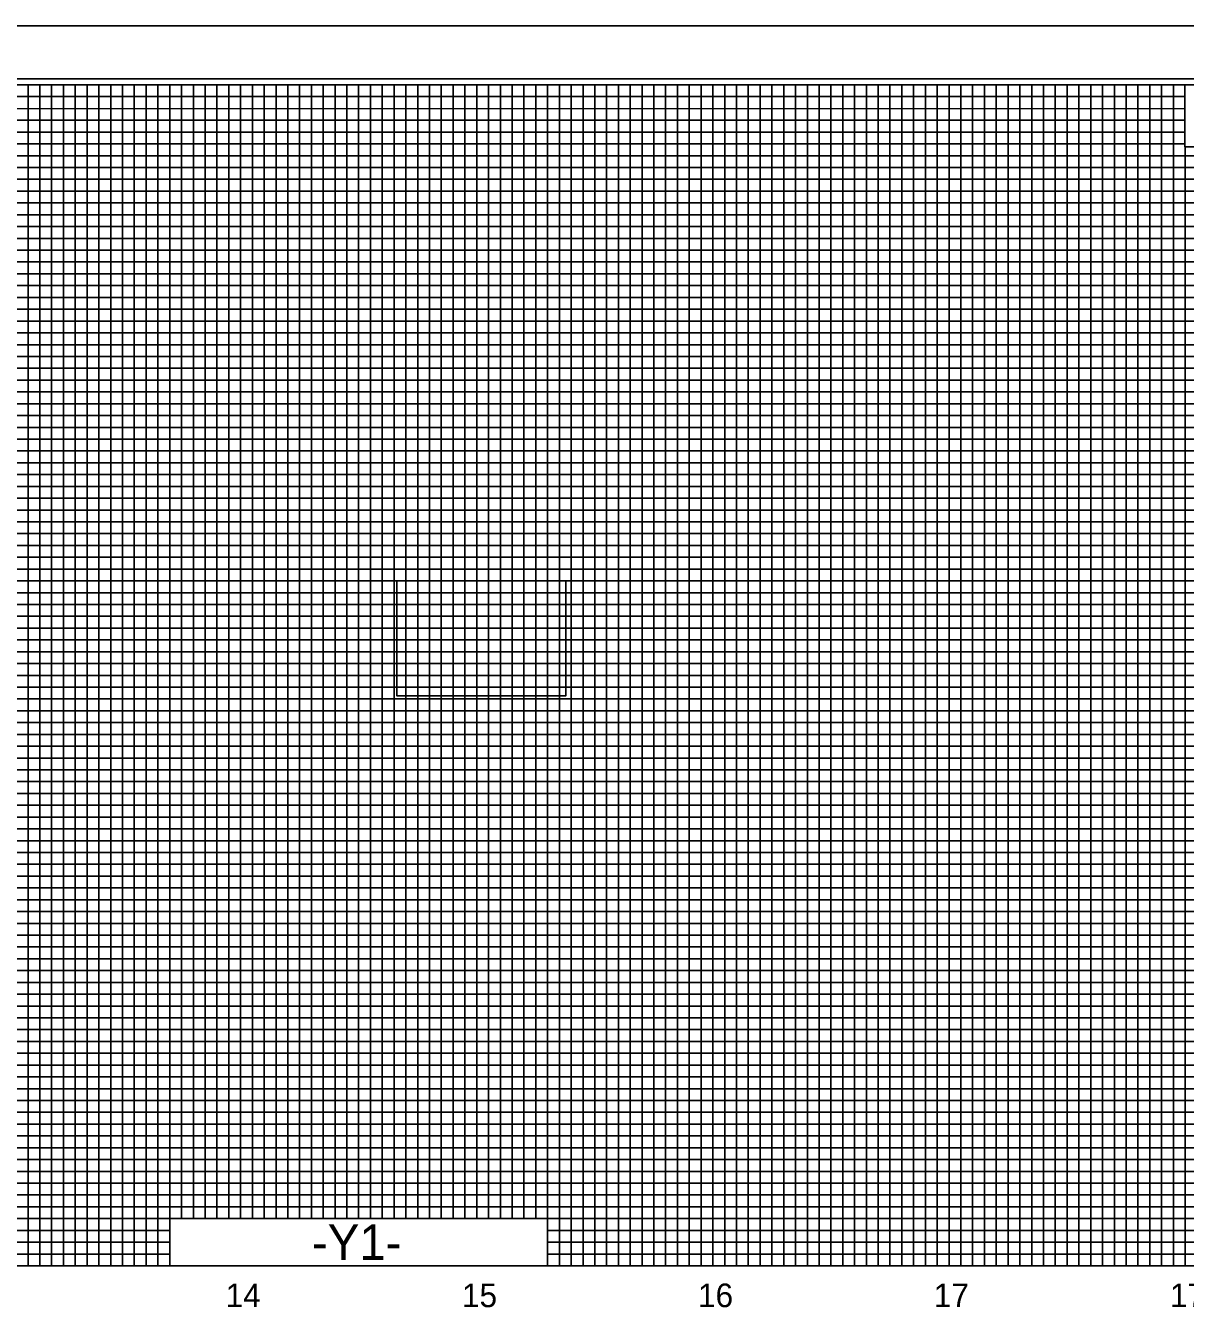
# Model space of a CAD drawing. Extents: x 1629737 to 1631945, y 1172886 to 1173986.
# Drawn here: x 1630513 to 1631004, y 1173440 to 1173986 of the extents above; entities that cross this region are included whole.
import ezdxf

# ---------------------------------------------------------------- set-up
doc = ezdxf.new("R2010")
doc.units = 0
for name, color, linetype in [('Exist Vertical Profile Horizontal Axis Label Major', 7, 'Continuous'), ('Prop Grid Mask', 7, 'Continuous'), ('Sheet Block Title CELL', 7, 'Continuous'), ('Sheet Data Field CELL', 7, 'Continuous'), ('Sheet Layout Profile Border Port 1', 7, 'Continuous'), ('Sheet Plot Border Inside CELL', 7, 'Continuous'), ('Sheet Plot Border Outside CELL', 7, 'Continuous'), ('Sheet Profile CELL', 7, 'Continuous'), ('Sheet Profile Grid Major CELL', 7, 'Continuous'), ('Sheet Profile Grid Middle CELL', 7, 'Continuous'), ('Sheet Profile Grid Minor CELL', 7, 'Continuous')]:
    doc.layers.add(name, color=color, linetype=linetype)

msp = doc.modelspace()

# ---------------------------------------------------------------- linework, layer by layer
at = {"layer": 'Prop Grid Mask'}
msp.add_lwpolyline([(1630670.53, 1173750.94), (1630742.03, 1173750.94), (1630742.03, 1173702.22), (1630670.53, 1173702.22)], close=True, dxfattribs=at)
at = {"layer": 'Sheet Block Title CELL'}
msp.add_lwpolyline([(1631004.21, 1173960.94), (1631204.26, 1173960.94), (1631204.26, 1173934.68), (1631004.21, 1173934.68)], close=True, dxfattribs=at)
at = {"layer": 'Sheet Data Field CELL'}
msp.add_lwpolyline([(1630574.31, 1173460.94), (1630734.31, 1173460.94), (1630734.31, 1173480.94), (1630574.31, 1173480.94)], close=True, dxfattribs=at)
at = {"layer": 'Sheet Layout Profile Border Port 1'}
msp.add_lwpolyline([(1629954.31, 1173960.94), (1631004.21, 1173960.94), (1631004.21, 1173934.68), (1631204.26, 1173934.68), (1631204.26, 1173799.89), (1631354.31, 1173799.89), (1631354.31, 1173485.94), (1631154.31, 1173485.94), (1631154.31, 1173460.94), (1630734.31, 1173460.94), (1630734.31, 1173480.94), (1630574.31, 1173480.94), (1630574.31, 1173460.94), (1629954.31, 1173460.94)], close=True, dxfattribs=at)
at = {"layer": 'Sheet Plot Border Inside CELL'}
msp.add_lwpolyline([(1629750.31, 1172908.39), (1631416.81, 1172908.39), (1631416.81, 1173963.49), (1629750.31, 1173963.49)], close=True, dxfattribs=at)
at = {"layer": 'Sheet Plot Border Outside CELL'}
msp.add_lwpolyline([(1629737.31, 1172885.94), (1631421.31, 1172885.94), (1631421.31, 1173985.94), (1629737.31, 1173985.94)], close=True, dxfattribs=at)
at = {"layer": 'Sheet Profile CELL'}
msp.add_line((1631404.31, 1173460.94), (1629904.31, 1173460.94), dxfattribs=at)
msp.add_lwpolyline([(1631404.31, 1173960.94), (1629904.31, 1173960.94), (1629904.31, 1172910.94), (1631404.31, 1172910.94)], close=True, dxfattribs=at)
at = {"layer": 'Sheet Profile Grid Major CELL'}
for p, q in [((1630504.31, 1173960.94), (1630554.31, 1173960.94)), ((1630554.31, 1173960.94), (1630554.31, 1173460.94)), ((1630604.31, 1173480.94), (1630604.31, 1173960.94)), ((1630604.31, 1173960.94), (1630654.31, 1173960.94)), ((1630654.31, 1173960.94), (1630654.31, 1173480.94)), ((1630704.31, 1173480.94), (1630704.31, 1173960.94)), ((1630704.31, 1173960.94), (1630754.31, 1173960.94)), ((1630754.31, 1173960.94), (1630754.31, 1173460.94)), ((1630804.31, 1173460.94), (1630804.31, 1173960.94)), ((1630804.31, 1173960.94), (1630854.31, 1173960.94)), ((1630854.31, 1173960.94), (1630854.31, 1173460.94)), ((1630904.31, 1173460.94), (1630904.31, 1173960.94)), ((1630904.31, 1173960.94), (1630954.31, 1173960.94)), ((1630954.31, 1173960.94), (1630954.31, 1173460.94)), ((1631004.31, 1173460.94), (1631004.31, 1173934.68)), ((1630554.31, 1173460.94), (1630584.31, 1173460.94)), ((1630754.31, 1173460.94), (1630804.31, 1173460.94)), ((1630854.31, 1173460.94), (1630904.31, 1173460.94)), ((1630954.31, 1173460.94), (1631004.31, 1173460.94))]:
    msp.add_line(p, q, dxfattribs=at)
for points in [[(1629904.31, 1173935.94), (1631004.21, 1173935.94)], [(1629904.31, 1173885.94), (1631204.26, 1173885.94)], [(1631204.26, 1173835.94), (1629904.31, 1173835.94), (1629904.31, 1173785.94), (1631404.31, 1173785.94)], [(1631404.31, 1173735.94), (1629904.31, 1173735.94), (1629904.31, 1173685.94), (1631404.31, 1173685.94)], [(1631404.31, 1173635.94), (1629904.31, 1173635.94), (1629904.31, 1173585.94), (1631404.31, 1173585.94)], [(1631404.31, 1173535.94), (1629904.31, 1173535.94), (1629904.31, 1173535.94), (1629904.31, 1173485.94), (1631404.31, 1173485.94)]]:
    msp.add_lwpolyline(points, dxfattribs=at)
at = {"layer": 'Sheet Profile Grid Middle CELL'}
msp.add_line((1629904.31, 1173960.94), (1631004.21, 1173960.94), dxfattribs=at)
for points in [[(1630479.31, 1173460.94), (1630529.31, 1173460.94), (1630529.31, 1173460.94), (1630529.31, 1173960.94), (1630579.31, 1173960.94), (1630579.31, 1173480.94)], [(1630629.31, 1173480.94), (1630629.31, 1173960.94), (1630679.31, 1173960.94), (1630679.31, 1173480.94)], [(1630729.31, 1173480.94), (1630729.31, 1173960.94), (1630779.31, 1173960.94), (1630779.31, 1173460.94), (1630829.31, 1173460.94), (1630829.31, 1173960.94), (1630879.31, 1173960.94), (1630879.31, 1173460.94), (1630929.31, 1173460.94), (1630929.31, 1173960.94), (1630979.31, 1173960.94), (1630979.31, 1173460.94), (1631029.31, 1173460.94), (1631029.31, 1173934.68)], [(1631204.26, 1173910.94), (1629904.31, 1173910.94), (1629904.31, 1173860.94), (1631204.26, 1173860.94)], [(1631204.26, 1173810.94), (1629904.31, 1173810.94), (1629904.31, 1173760.94), (1631404.31, 1173760.94)], [(1631404.31, 1173710.94), (1629904.31, 1173710.94), (1629904.31, 1173660.94), (1631404.31, 1173660.94)], [(1631404.31, 1173610.94), (1629904.31, 1173610.94), (1629904.31, 1173560.94), (1631404.31, 1173560.94)], [(1631404.31, 1173510.94), (1629904.31, 1173510.94)]]:
    msp.add_lwpolyline(points, dxfattribs=at)
at = {"layer": 'Sheet Profile Grid Minor CELL'}
for p, q in [((1630514.31, 1173460.94), (1630514.31, 1173960.94)), ((1630514.31, 1173960.94), (1630519.31, 1173960.94)), ((1630519.31, 1173960.94), (1630519.31, 1173460.94)), ((1630524.31, 1173460.94), (1630524.31, 1173960.94)), ((1630524.31, 1173960.94), (1630534.31, 1173960.94)), ((1630534.31, 1173960.94), (1630534.31, 1173460.94)), ((1630539.31, 1173460.94), (1630539.31, 1173960.94)), ((1630539.31, 1173960.94), (1630544.31, 1173960.94)), ((1630544.31, 1173960.94), (1630544.31, 1173460.94)), ((1630549.31, 1173460.94), (1630549.31, 1173960.94)), ((1630549.31, 1173960.94), (1630559.31, 1173960.94)), ((1630559.31, 1173960.94), (1630559.31, 1173460.94)), ((1630564.31, 1173460.94), (1630564.31, 1173960.94)), ((1630564.31, 1173960.94), (1630569.31, 1173960.94)), ((1630569.31, 1173960.94), (1630569.31, 1173460.94)), ((1630574.31, 1173460.94), (1630574.31, 1173960.94)), ((1630574.31, 1173960.94), (1630584.31, 1173960.94)), ((1630584.31, 1173960.94), (1630584.31, 1173480.94)), ((1630589.31, 1173480.94), (1630589.31, 1173960.94)), ((1630589.31, 1173960.94), (1630594.31, 1173960.94)), ((1630594.31, 1173960.94), (1630594.31, 1173480.94)), ((1630599.31, 1173480.94), (1630599.31, 1173960.94)), ((1630599.31, 1173960.94), (1630609.31, 1173960.94)), ((1630609.31, 1173960.94), (1630609.31, 1173480.94)), ((1630699.31, 1173480.94), (1630699.31, 1173960.94)), ((1630699.31, 1173960.94), (1630709.31, 1173960.94)), ((1630709.31, 1173960.94), (1630709.31, 1173480.94)), ((1630714.31, 1173480.94), (1630714.31, 1173960.94)), ((1630714.31, 1173960.94), (1630719.31, 1173960.94)), ((1630719.31, 1173960.94), (1630719.31, 1173480.94)), ((1630724.31, 1173480.94), (1630724.31, 1173960.94)), ((1630724.31, 1173960.94), (1630734.31, 1173960.94)), ((1630734.31, 1173960.94), (1630734.31, 1173460.94)), ((1630739.31, 1173460.94), (1630739.31, 1173960.94)), ((1630739.31, 1173960.94), (1630744.31, 1173960.94)), ((1630744.31, 1173960.94), (1630744.31, 1173460.94)), ((1630749.31, 1173460.94), (1630749.31, 1173960.94)), ((1630749.31, 1173960.94), (1630759.31, 1173960.94)), ((1630759.31, 1173960.94), (1630759.31, 1173460.94)), ((1630764.31, 1173460.94), (1630764.31, 1173960.94)), ((1630764.31, 1173960.94), (1630769.31, 1173960.94)), ((1630769.31, 1173960.94), (1630769.31, 1173460.94)), ((1630774.31, 1173460.94), (1630774.31, 1173960.94)), ((1630774.31, 1173960.94), (1630784.31, 1173960.94)), ((1630784.31, 1173960.94), (1630784.31, 1173460.94)), ((1629954.31, 1173955.94), (1631004.21, 1173955.94)), ((1631004.21, 1173950.88), (1629954.31, 1173950.59)), ((1629954.31, 1173945.94), (1631004.21, 1173945.94)), ((1631204.31, 1173825.94), (1629954.31, 1173825.94)), ((1631204.31, 1173820.94), (1629954.31, 1173820.94)), ((1631204.31, 1173815.94), (1629954.31, 1173815.94)), ((1629954.31, 1173805.94), (1631204.31, 1173805.94)), ((1631204.31, 1173800.94), (1629954.31, 1173800.94)), ((1629954.31, 1173795.94), (1631354.31, 1173795.94)), ((1631354.31, 1173775.94), (1629954.31, 1173775.94)), ((1629954.31, 1173770.94), (1631354.31, 1173770.94)), ((1631354.31, 1173750.94), (1629954.31, 1173750.94)), ((1629954.31, 1173745.94), (1631354.31, 1173745.94)), ((1631354.31, 1173725.94), (1629954.31, 1173725.94)), ((1629954.31, 1173720.94), (1631354.31, 1173720.94)), ((1631354.31, 1173715.94), (1629954.31, 1173715.94)), ((1629954.31, 1173705.94), (1631354.31, 1173705.94)), ((1631354.31, 1173700.94), (1629954.31, 1173700.94)), ((1629954.31, 1173695.94), (1631354.31, 1173695.94)), ((1631354.31, 1173690.94), (1629954.31, 1173690.94)), ((1629954.31, 1173680.94), (1631354.31, 1173680.94)), ((1631354.31, 1173675.94), (1629954.31, 1173675.94)), ((1629954.31, 1173670.94), (1631354.31, 1173670.94)), ((1631354.31, 1173665.94), (1629954.31, 1173665.94)), ((1629954.31, 1173655.94), (1631354.31, 1173655.94)), ((1631354.31, 1173650.94), (1629954.31, 1173650.94)), ((1629954.31, 1173645.94), (1631354.31, 1173645.94)), ((1631354.31, 1173640.94), (1629954.31, 1173640.94)), ((1629954.31, 1173630.94), (1631354.31, 1173630.94)), ((1631354.31, 1173625.94), (1629954.31, 1173625.94)), ((1629954.31, 1173620.94), (1631354.31, 1173620.94)), ((1631354.31, 1173615.94), (1629954.31, 1173615.94)), ((1629954.31, 1173605.94), (1631354.31, 1173605.94)), ((1631354.31, 1173600.94), (1629954.31, 1173600.94)), ((1629954.31, 1173595.94), (1631354.31, 1173595.94)), ((1631354.31, 1173590.94), (1629954.31, 1173590.94)), ((1629954.31, 1173580.94), (1631354.31, 1173580.94)), ((1631354.31, 1173575.94), (1629954.31, 1173575.94)), ((1631354.31, 1173570.94), (1629954.31, 1173570.94)), ((1631354.31, 1173565.94), (1629954.31, 1173565.94)), ((1629954.31, 1173555.94), (1631354.31, 1173555.94)), ((1631354.31, 1173550.94), (1629954.31, 1173550.94)), ((1629954.31, 1173545.94), (1631354.31, 1173545.94)), ((1631354.31, 1173540.94), (1629954.31, 1173540.94)), ((1629954.31, 1173530.94), (1631354.31, 1173530.94)), ((1631354.31, 1173525.94), (1629954.31, 1173525.94)), ((1629954.31, 1173520.94), (1631354.31, 1173520.94)), ((1631354.31, 1173515.94), (1629954.31, 1173515.94)), ((1629954.31, 1173505.94), (1631354.31, 1173505.94)), ((1631354.31, 1173500.94), (1629954.31, 1173500.94)), ((1629954.31, 1173495.94), (1631354.31, 1173495.94)), ((1631354.31, 1173490.94), (1629954.31, 1173490.94)), ((1629954.31, 1173480.94), (1631154.31, 1173480.94)), ((1630574.31, 1173475.94), (1629954.31, 1173475.94)), ((1631154.31, 1173475.94), (1630734.31, 1173475.94)), ((1629954.31, 1173470.94), (1630574.31, 1173470.94)), ((1630734.31, 1173470.94), (1631154.31, 1173470.94)), ((1630509.31, 1173460.94), (1630514.31, 1173460.94)), ((1630519.31, 1173460.94), (1630524.31, 1173460.94)), ((1630534.31, 1173460.94), (1630539.31, 1173460.94)), ((1630544.31, 1173460.94), (1630549.31, 1173460.94)), ((1630559.31, 1173460.94), (1630564.31, 1173460.94)), ((1630569.31, 1173460.94), (1630574.31, 1173460.94)), ((1630584.31, 1173460.94), (1630589.31, 1173460.94)), ((1630594.31, 1173460.94), (1630599.31, 1173460.94)), ((1630734.31, 1173460.94), (1630739.31, 1173460.94)), ((1630744.31, 1173460.94), (1630749.31, 1173460.94)), ((1630759.31, 1173460.94), (1630764.31, 1173460.94)), ((1630769.31, 1173460.94), (1630774.31, 1173460.94)), ((1630784.31, 1173460.94), (1630789.31, 1173460.94))]:
    msp.add_line(p, q, dxfattribs=at)
for points in [[(1630614.31, 1173480.94), (1630614.31, 1173960.94), (1630619.31, 1173960.94), (1630619.31, 1173480.94)], [(1630624.31, 1173480.94), (1630624.31, 1173960.94), (1630634.31, 1173960.94), (1630634.31, 1173480.94)], [(1630639.31, 1173480.94), (1630639.31, 1173960.94), (1630644.31, 1173960.94), (1630644.31, 1173480.94)], [(1630649.31, 1173480.94), (1630649.31, 1173960.94), (1630659.31, 1173960.94), (1630659.31, 1173480.94)], [(1630664.31, 1173480.94), (1630664.31, 1173960.94), (1630669.31, 1173960.94), (1630669.31, 1173480.94)], [(1630674.31, 1173480.94), (1630674.31, 1173960.94), (1630684.31, 1173960.94), (1630684.31, 1173480.94)], [(1630689.31, 1173480.94), (1630689.31, 1173960.94), (1630694.31, 1173960.94), (1630694.31, 1173480.94)], [(1630789.31, 1173460.94), (1630789.31, 1173960.94), (1630794.31, 1173960.94), (1630794.31, 1173460.94), (1630799.31, 1173460.94), (1630799.31, 1173960.94), (1630809.31, 1173960.94), (1630809.31, 1173460.94), (1630814.31, 1173460.94), (1630814.31, 1173960.94), (1630819.31, 1173960.94), (1630819.31, 1173460.94), (1630824.31, 1173460.94), (1630824.31, 1173960.94), (1630834.31, 1173960.94), (1630834.31, 1173460.94), (1630839.31, 1173460.94), (1630839.31, 1173960.94), (1630844.31, 1173960.94), (1630844.31, 1173460.94), (1630849.31, 1173460.94), (1630849.31, 1173960.94), (1630859.31, 1173960.94), (1630859.31, 1173460.94), (1630864.31, 1173460.94), (1630864.31, 1173960.94), (1630869.31, 1173960.94), (1630869.31, 1173460.94), (1630874.31, 1173460.94), (1630874.31, 1173960.94), (1630884.31, 1173960.94), (1630884.31, 1173460.94), (1630889.31, 1173460.94), (1630889.31, 1173960.94), (1630894.31, 1173960.94), (1630894.31, 1173460.94), (1630899.31, 1173460.94), (1630899.31, 1173960.94), (1630909.31, 1173960.94), (1630909.31, 1173460.94), (1630914.31, 1173460.94), (1630914.31, 1173960.94), (1630919.31, 1173960.94), (1630919.31, 1173460.94), (1630924.31, 1173460.94), (1630924.31, 1173960.94), (1630934.31, 1173960.94), (1630934.31, 1173460.94), (1630939.31, 1173460.94), (1630939.31, 1173960.94), (1630944.31, 1173960.94), (1630944.31, 1173460.94), (1630949.31, 1173460.94), (1630949.31, 1173960.94), (1630959.31, 1173960.94), (1630959.31, 1173460.94), (1630964.31, 1173460.94), (1630964.31, 1173960.94), (1630969.31, 1173960.94), (1630969.31, 1173460.94), (1630974.31, 1173460.94), (1630974.31, 1173960.94), (1630984.31, 1173960.94), (1630984.31, 1173460.94), (1630989.31, 1173460.94), (1630989.31, 1173960.94), (1630994.31, 1173960.94), (1630994.31, 1173460.94), (1630999.31, 1173460.94), (1630999.31, 1173960.94), (1631004.31, 1173960.94)], [(1631004.21, 1173940.94), (1629954.31, 1173940.94), (1629954.31, 1173930.94), (1631204.26, 1173930.94)], [(1631204.26, 1173925.94), (1629954.31, 1173925.94), (1629954.31, 1173920.94), (1631204.26, 1173920.94)], [(1631204.26, 1173915.94), (1629954.31, 1173915.94), (1629954.31, 1173905.94), (1631204.26, 1173905.94)], [(1631204.26, 1173900.94), (1629954.31, 1173900.94), (1629954.31, 1173895.94), (1631204.26, 1173895.94)], [(1631204.26, 1173890.94), (1629954.31, 1173890.94), (1629954.31, 1173880.94), (1631204.26, 1173880.94)], [(1631204.26, 1173875.94), (1629954.31, 1173875.94), (1629954.31, 1173870.94), (1631204.26, 1173870.94)], [(1631204.26, 1173865.94), (1629954.31, 1173865.94), (1629954.31, 1173855.94), (1631204.26, 1173855.94)], [(1631204.26, 1173850.84), (1629954.41, 1173850.84), (1629954.41, 1173845.94), (1631204.26, 1173845.94)], [(1631204.26, 1173840.94), (1629954.31, 1173840.94), (1629954.31, 1173830.94), (1631204.26, 1173830.94)], [(1631354.31, 1173790.94), (1629954.31, 1173790.94), (1629954.31, 1173780.94), (1631354.31, 1173780.94)], [(1631354.31, 1173765.94), (1629954.31, 1173765.94), (1629954.31, 1173755.94), (1631354.31, 1173755.94)], [(1631354.31, 1173740.94), (1629954.31, 1173740.94), (1629954.31, 1173730.94), (1631354.31, 1173730.94)], [(1630574.31, 1173465.94), (1629954.31, 1173465.94)], [(1631154.31, 1173465.94), (1630734.31, 1173465.94)]]:
    msp.add_lwpolyline(points, dxfattribs=at)

# ---------------------------------------------------------------- texts
at = {"layer": 'Exist Vertical Profile Horizontal Axis Label Major'}
for s, p in [('14', (1630597.96, 1173443.44)), ('15', (1630698.05, 1173443.44)), ('16', (1630798, 1173443.44)), ('17', (1630897.85, 1173443.44)), ('17', (1630997.85, 1173443.44))]:
    msp.add_text(s, height=10, dxfattribs=at).set_placement(p)
at = {"layer": 'Sheet Data Field CELL'}
msp.add_text('-Y1-', height=15, rotation=360, dxfattribs=at).set_placement((1630634.54, 1173463.44))

doc.saveas('drawing.dxf')
